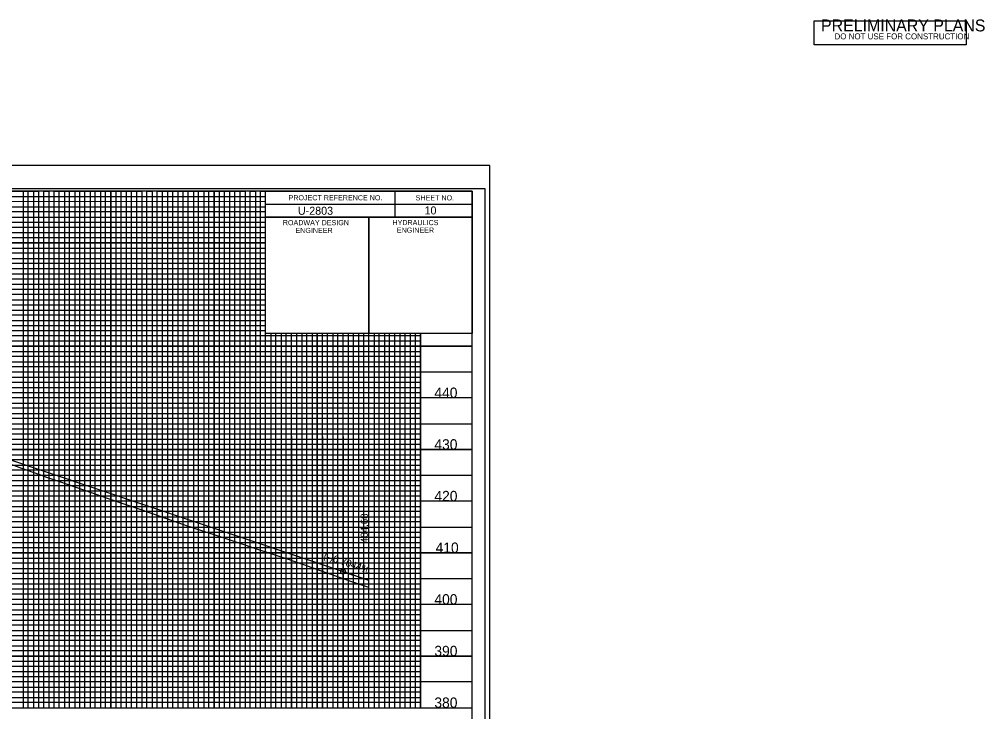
# Model space of a CAD drawing. Extents: x 571503 to 593215, y -77195 to -51828.
# Drawn here: x 583558 to 584493, y -73444 to -72774 of the extents above; entities that cross this region are included whole.
import ezdxf

# ---------------------------------------------------------------- set-up
doc = ezdxf.new("R2010")
doc.units = 0
for name, color, linetype in [('Exist Vertical Profile Ground Line', 7, 'Continuous'), ('Exist Vertical Profile Vertical Axis Label', 7, 'Continuous'), ('Prop Vertical Profile Curve Label', 7, 'Continuous'), ('Prop Vertical Profile Grade', 7, 'Continuous'), ('Prop Vertical Profile Grade Label', 7, 'Continuous'), ('Prop VPI Label', 7, 'Continuous'), ('Sheet Cutting Line CELL', 7, 'Continuous'), ('Sheet Data Field CELL', 7, 'Continuous'), ('Sheet DOT Grid CELL', 7, 'Continuous'), ('Sheet Layout Profile Border Port 1', 7, 'Continuous'), ('Sheet Plot Border Inside CELL', 7, 'Continuous'), ('Sheet Plot Border Outside CELL', 7, 'Continuous'), ('Sheet Profile CELL', 7, 'Continuous'), ('Sheet Profile Grid Major CELL', 7, 'Continuous'), ('Sheet Profile Grid Middle CELL', 7, 'Continuous'), ('Sheet Profile Grid Minor CELL', 7, 'Continuous'), ('Sheet Sticker Preliminary CELL', 7, 'Continuous')]:
    doc.layers.add(name, color=color, linetype=linetype)

msp = doc.modelspace()

# ---------------------------------------------------------------- linework, layer by layer
at = {"layer": 'Exist Vertical Profile Ground Line'}
msp.add_lwpolyline([(583546.65, -73202.89), (583560.54, -73207.95), (583578.03, -73214.22), (583584.69, -73216.65), (583597.14, -73220.9), (583612.11, -73226.16), (583629.03, -73231.94), (583637.11, -73234.78), (583645.46, -73237.64), (583660.73, -73242.98), (583677.05, -73248.56), (583685.27, -73251.43), (583689.87, -73253.04), (583705.42, -73258.32), (583722.05, -73264.12), (583724.42, -73264.93), (583728.62, -73266.35), (583743.88, -73271.4), (583760.39, -73276.98), (583770.95, -73280.48), (583787.27, -73286), (583802.9, -73290.98), (583809.77, -73293.33), (583817.86, -73295.91), (583833.67, -73301.33), (583849.88, -73307.04), (583857.24, -73309.62), (583864.77, -73312.28), (583880.15, -73317.68), (583896.73, -73323.36), (583896.98, -73323.45)], dxfattribs=at)
at = {"layer": 'Prop Vertical Profile Curve Label'}
msp.add_circle((583871.98, -73308.26), 2.25, dxfattribs=at)
at = {"layer": 'Prop Vertical Profile Grade'}
msp.add_line((583521.98, -73190.93), (583871.98, -73308.26), dxfattribs=at)
msp.add_open_spline([(583871.98, -73308.26), (583873.75, -73308.85), (583875.52, -73309.45), (583877.28, -73310.04), (583879.05, -73310.63), (583880.82, -73311.23), (583882.58, -73311.82), (583884.35, -73312.41), (583886.12, -73313.01), (583887.88, -73313.6), (583889.65, -73314.2), (583891.42, -73314.79), (583893.18, -73315.39), (583894.45, -73315.82), (583895.72, -73316.25), (583896.98, -73316.67)], degree=3, dxfattribs=at)
at = {"layer": 'Prop VPI Label'}
msp.add_line((583871.98, -73308.26), (583896.98, -73316.64), dxfattribs=at)
at = {"layer": 'Sheet Cutting Line CELL'}
msp.add_line((584013.98, -72915.09), (582329.98, -72915.09), dxfattribs=at)
at = {"layer": 'Sheet DOT Grid CELL'}
for p, q in [((583596.98, -73440.09), (583596.98, -72940.09)), ((583646.98, -73440.09), (583646.98, -72940.09)), ((583696.98, -73440.09), (583696.98, -72940.09)), ((583746.98, -73440.09), (583746.98, -72940.09)), ((583796.93, -72990.09), (582496.98, -72990.09)), ((583796.93, -73040.09), (582496.98, -73040.09)), ((583796.98, -73440.09), (583796.98, -73077.64)), ((583846.98, -73440.09), (583846.98, -73077.64)), ((583896.98, -73440.09), (583896.98, -73077.64)), ((583946.98, -73440.09), (583946.98, -73077.64)), ((583996.98, -73090.09), (582496.98, -73090.09)), ((583996.98, -73140.09), (582496.98, -73140.09)), ((583996.98, -73190.09), (582496.98, -73190.09)), ((583996.98, -73240.09), (582496.98, -73240.09)), ((583996.98, -73290.09), (582496.98, -73290.09)), ((583996.98, -73340.09), (582496.98, -73340.09)), ((583996.98, -73390.09), (582496.98, -73390.09))]:
    msp.add_line(p, q, dxfattribs=at)
at = {"layer": 'Sheet Layout Profile Border Port 1'}
msp.add_lwpolyline([(582546.98, -72940.09), (582546.98, -73440.09), (583946.98, -73440.09), (583946.98, -73077.64), (583796.93, -73077.64), (583796.93, -72940.09)], close=True, dxfattribs=at)
at = {"layer": 'Sheet Plot Border Inside CELL'}
msp.add_lwpolyline([(582342.98, -73992.64), (584009.48, -73992.64), (584009.48, -72937.54), (582342.98, -72937.54)], close=True, dxfattribs=at)
at = {"layer": 'Sheet Plot Border Outside CELL'}
msp.add_lwpolyline([(582329.98, -74015.09), (584013.98, -74015.09), (584013.98, -72915.09), (582329.98, -72915.09)], close=True, dxfattribs=at)
at = {"layer": 'Sheet Profile CELL'}
for p, q in [((583921.98, -72940.14), (583921.98, -72965.14)), ((583796.93, -72952.64), (583996.98, -72952.64)), ((583896.98, -72965.14), (583896.98, -73077.59)), ((582496.98, -73440.09), (583996.98, -73440.09))]:
    msp.add_line(p, q, dxfattribs=at)
for points in [[(583996.98, -72940.09), (582496.98, -72940.09), (582496.98, -73990.09), (583996.98, -73990.09)], [(583796.93, -72940.09), (583996.98, -72940.09), (583996.98, -72965.14), (583796.93, -72965.14)], [(583796.93, -72965.14), (583896.98, -72965.14), (583896.98, -73077.64), (583796.93, -73077.64)], [(583896.98, -72965.14), (583996.98, -72965.14), (583996.98, -73077.64), (583896.98, -73077.64)]]:
    msp.add_lwpolyline(points, close=True, dxfattribs=at)
at = {"layer": 'Sheet Profile Grid Major CELL'}
for points in [[(583546.98, -73440.09), (583596.98, -73440.09), (583596.98, -72940.09), (583646.98, -72940.09), (583646.98, -73440.09), (583696.98, -73440.09), (583696.98, -72940.09), (583746.98, -72940.09), (583746.98, -73440.09), (583796.98, -73440.09), (583796.98, -72940.09), (583823.28, -72940.09)], [(582496.98, -72990.09), (583796.98, -72990.09)], [(583796.98, -73040.09), (582496.98, -73040.09), (582496.98, -73090.09), (583996.98, -73090.09)], [(583846.98, -73077.64), (583846.98, -73440.09), (583896.98, -73440.09), (583896.98, -73440.09), (583896.98, -73077.64)], [(583946.98, -73077.64), (583946.98, -73440.09), (583996.98, -73440.09), (583996.98, -73090.09)], [(583996.98, -73140.09), (582496.98, -73140.09), (582496.98, -73190.09), (583996.98, -73190.09)], [(583996.98, -73240.09), (582496.98, -73240.09), (582496.98, -73290.09), (583996.98, -73290.09)], [(583996.98, -73340.09), (582496.98, -73340.09), (582496.98, -73340.09), (582496.98, -73390.09), (583996.98, -73390.09)]]:
    msp.add_lwpolyline(points, dxfattribs=at)
at = {"layer": 'Sheet Profile Grid Middle CELL'}
msp.add_line((582496.98, -72965.09), (583796.93, -72965.09), dxfattribs=at)
for points in [[(583521.98, -72940.09), (583571.98, -72940.09), (583571.98, -73440.09), (583621.98, -73440.09), (583621.98, -72940.09), (583671.98, -72940.09), (583671.98, -73440.09), (583721.98, -73440.09), (583721.98, -72940.09), (583771.98, -72940.09), (583771.98, -73440.09), (583821.98, -73440.09), (583821.98, -73077.64)], [(583796.98, -73015.09), (582496.98, -73015.09), (582496.98, -73065.09), (583796.98, -73065.09)], [(583821.98, -73177.29), (583821.98, -73440.09), (583871.98, -73440.09), (583871.98, -73077.64)], [(583871.98, -73177.29), (583871.98, -73440.09), (583921.98, -73440.09), (583921.98, -73077.64)], [(583996.98, -73115.09), (582496.98, -73115.09), (582496.98, -73165.09), (583821.98, -73165.09)], [(583821.98, -73165.09), (583996.98, -73165.09)], [(583996.98, -73215.09), (582496.98, -73215.09), (582496.98, -73265.09), (583996.98, -73265.09)], [(583996.98, -73315.09), (582496.98, -73315.09), (582496.98, -73365.09), (583996.98, -73365.09)], [(583996.98, -73415.09), (582496.98, -73415.09)]]:
    msp.add_lwpolyline(points, dxfattribs=at)
at = {"layer": 'Sheet Profile Grid Minor CELL'}
for p, q in [((582546.98, -72945.09), (583796.98, -72945.09)), ((583796.98, -72950.09), (582546.98, -72950.44)), ((582546.98, -72955.09), (583796.98, -72955.09)), ((583796.93, -73075.09), (582546.98, -73075.09)), ((583946.98, -73080.09), (582546.98, -73080.09)), ((583946.98, -73085.09), (582546.98, -73085.09)), ((582546.98, -73095.09), (583946.98, -73095.09)), ((583946.98, -73100.09), (582546.98, -73100.09)), ((582546.98, -73105.09), (583946.98, -73105.09)), ((583946.98, -73125.09), (582546.98, -73125.09)), ((582546.98, -73130.09), (583946.98, -73130.09)), ((583946.98, -73150.09), (582546.98, -73150.09)), ((582546.98, -73155.09), (583946.98, -73155.09)), ((583946.98, -73175.09), (582546.98, -73175.09)), ((582546.98, -73180.09), (583946.98, -73180.09)), ((583946.98, -73185.09), (582546.98, -73185.09)), ((582546.98, -73195.09), (583946.98, -73195.09)), ((583946.98, -73200.09), (582546.98, -73200.09)), ((582546.98, -73205.09), (583946.98, -73205.09)), ((583946.98, -73210.09), (582546.98, -73210.09)), ((582546.98, -73220.09), (583946.98, -73220.09)), ((583946.98, -73225.09), (582546.98, -73225.09)), ((582546.98, -73230.09), (583946.98, -73230.09)), ((583946.98, -73235.09), (582546.98, -73235.09)), ((582546.98, -73245.09), (583946.98, -73245.09)), ((583946.98, -73250.09), (582546.98, -73250.09)), ((582546.98, -73255.09), (583946.98, -73255.09)), ((583946.98, -73260.09), (582546.98, -73260.09)), ((582546.98, -73270.09), (583946.98, -73270.09)), ((583946.98, -73275.09), (582546.98, -73275.09)), ((582546.98, -73280.09), (583946.98, -73280.09)), ((583946.98, -73285.09), (582546.98, -73285.09)), ((582546.98, -73295.09), (583946.98, -73295.09)), ((583946.98, -73300.09), (582546.98, -73300.09)), ((582546.98, -73305.09), (583946.98, -73305.09)), ((583946.98, -73310.09), (582546.98, -73310.09)), ((582546.98, -73320.09), (583946.98, -73320.09)), ((583946.98, -73325.09), (582546.98, -73325.09)), ((583946.98, -73330.09), (582546.98, -73330.09)), ((583946.98, -73335.09), (582546.98, -73335.09)), ((582546.98, -73345.09), (583946.98, -73345.09)), ((583946.98, -73350.09), (582546.98, -73350.09)), ((582546.98, -73355.09), (583946.98, -73355.09)), ((583946.98, -73360.09), (582546.98, -73360.09)), ((582546.98, -73370.09), (583946.98, -73370.09)), ((583946.98, -73375.09), (582546.98, -73375.09)), ((582546.98, -73380.09), (583946.98, -73380.09)), ((583946.98, -73385.09), (582546.98, -73385.09)), ((582546.98, -73395.09), (583946.98, -73395.09)), ((583946.98, -73400.09), (582546.98, -73400.09)), ((582546.98, -73405.09), (583946.98, -73405.09)), ((583946.98, -73410.09), (582546.98, -73410.09)), ((582546.98, -73420.09), (583946.98, -73420.09)), ((583946.98, -73425.09), (582546.98, -73425.09)), ((582546.98, -73430.09), (583946.98, -73430.09))]:
    msp.add_line(p, q, dxfattribs=at)
for points in [[(583556.98, -72940.09), (583561.98, -72940.09), (583561.98, -73440.09), (583566.98, -73440.09), (583566.98, -72940.09), (583576.98, -72940.09), (583576.98, -73440.09), (583581.98, -73440.09), (583581.98, -72940.09), (583586.98, -72940.09), (583586.98, -73440.09), (583591.98, -73440.09), (583591.98, -72940.09), (583601.98, -72940.09), (583601.98, -73440.09), (583606.98, -73440.09), (583606.98, -72940.09), (583611.98, -72940.09), (583611.98, -73440.09), (583616.98, -73440.09), (583616.98, -72940.09), (583626.98, -72940.09), (583626.98, -73440.09), (583631.98, -73440.09), (583631.98, -72940.09), (583636.98, -72940.09), (583636.98, -73440.09), (583641.98, -73440.09), (583641.98, -72940.09), (583651.98, -72940.09), (583651.98, -73440.09), (583656.98, -73440.09), (583656.98, -72940.09), (583661.98, -72940.09), (583661.98, -73440.09), (583666.98, -73440.09), (583666.98, -72940.09), (583676.98, -72940.09), (583676.98, -73440.09), (583681.98, -73440.09), (583681.98, -72940.09), (583686.98, -72940.09), (583686.98, -73440.09)], [(583686.98, -73440.09), (583691.98, -73440.09), (583691.98, -72940.09), (583701.98, -72940.09), (583701.98, -73440.09), (583706.98, -73440.09), (583706.98, -72940.09), (583711.98, -72940.09), (583711.98, -73440.09), (583716.98, -73440.09), (583716.98, -72940.09), (583726.98, -72940.09), (583726.98, -73440.09), (583731.98, -73440.09), (583731.98, -72940.09), (583736.98, -72940.09), (583736.98, -73440.09), (583741.98, -73440.09), (583741.98, -72940.09), (583751.98, -72940.09), (583751.98, -73440.09), (583756.98, -73440.09), (583756.98, -72940.09), (583761.98, -72940.09), (583761.98, -73440.09), (583766.98, -73440.09), (583766.98, -72940.09), (583776.98, -72940.09), (583776.98, -73440.09), (583781.98, -73440.09), (583781.98, -72940.09), (583786.98, -72940.09), (583786.98, -73440.09), (583791.98, -73440.09), (583791.98, -72940.09), (583801.98, -72940.09)], [(583796.98, -72960.09), (582546.98, -72960.09), (582546.98, -72970.09), (583796.98, -72970.09)], [(583796.93, -72975.09), (582546.98, -72975.09), (582546.98, -72980.09), (583796.98, -72980.09)], [(583796.98, -72985.09), (582546.98, -72985.09), (582546.98, -72995.09), (583796.98, -72995.09)], [(583796.98, -73000.09), (582546.98, -73000.09), (582546.98, -73005.09), (583796.98, -73005.09)], [(583796.98, -73010.09), (582546.98, -73010.09), (582546.98, -73020.09), (583796.98, -73020.09)], [(583796.98, -73025.09), (582546.98, -73025.09), (582546.98, -73030.09), (583796.98, -73030.09)], [(583796.98, -73035.09), (582546.98, -73035.09), (582546.98, -73045.09), (583796.98, -73045.09)], [(583796.98, -73050.19), (582547.08, -73050.19), (582547.08, -73055.09), (583796.98, -73055.09)], [(583796.98, -73060.09), (582546.98, -73060.09), (582546.98, -73070.09), (583796.98, -73070.09)], [(583801.98, -73077.64), (583801.98, -73440.09), (583806.98, -73440.09), (583806.98, -73077.64)], [(583811.98, -73077.64), (583811.98, -73440.09), (583816.98, -73440.09), (583816.98, -73077.64)], [(583826.98, -73077.64), (583826.98, -73440.09), (583826.98, -73440.09), (583831.98, -73440.09), (583836.98, -73440.09), (583836.98, -73077.64)], [(583831.98, -73077.64), (583831.98, -73440.09)], [(583841.98, -73077.64), (583841.88, -73440.04), (583846.88, -73440.04), (583851.98, -73440.09), (583851.98, -73077.64)], [(583851.98, -73177.29), (583851.98, -73440.09), (583856.98, -73440.09), (583856.98, -73077.64)], [(583861.98, -73077.64), (583861.98, -73440.09), (583866.98, -73440.09), (583866.98, -73077.64)], [(583876.98, -73077.64), (583876.98, -73440.09), (583881.98, -73440.09), (583881.98, -73077.64)], [(583886.98, -73077.64), (583886.98, -73440.09), (583891.98, -73440.09), (583891.98, -73077.64)], [(583901.98, -73077.64), (583901.98, -73440.09), (583906.98, -73440.09), (583906.98, -73077.64)], [(583911.98, -73077.64), (583911.98, -73440.09), (583916.98, -73440.09), (583916.98, -73077.64)], [(583926.98, -73077.64), (583926.98, -73440.09), (583931.98, -73440.09), (583931.98, -73077.64)], [(583936.98, -73077.64), (583936.98, -73440.09), (583941.98, -73440.09), (583941.98, -73077.64)], [(583946.98, -73110.09), (582546.98, -73110.09), (582546.98, -73120.09), (583946.98, -73120.09)], [(583946.98, -73135.09), (582546.98, -73135.09), (582546.98, -73145.09), (583946.98, -73145.09)], [(583946.98, -73160.09), (582546.98, -73160.09), (582546.98, -73170.09), (583946.98, -73170.09)], [(583946.98, -73435.09), (582546.98, -73435.09)]]:
    msp.add_lwpolyline(points, dxfattribs=at)
at = {"layer": 'Sheet Sticker Preliminary CELL'}
msp.add_lwpolyline([(584328.41, -72798.41), (584328.41, -72774.91), (584475.41, -72774.91), (584475.41, -72798.41)], close=True, dxfattribs=at)

# ---------------------------------------------------------------- texts
at = {"layer": 'Exist Vertical Profile Vertical Axis Label'}
for s, p in [('440', (583960.42, -73140.09)), ('430', (583960.42, -73190.09)), ('420', (583960.42, -73240.09)), ('410', (583961.61, -73290.09)), ('400', (583960.42, -73340.09)), ('390', (583960.42, -73390.09)), ('380', (583960.42, -73440.09))]:
    msp.add_text(s, height=10, dxfattribs=at).set_placement(p)
at = {"layer": 'Prop Vertical Profile Grade Label'}
msp.add_text('(-)6.7044%', height=7, rotation=341.46781, dxfattribs=at).set_placement((583852.63, -73295.58))
at = {"layer": 'Prop VPI Label'}
msp.add_text('404.68', height=7, rotation=90, dxfattribs=at).set_placement((583895.98, -73280.6))
at = {"layer": 'Sheet Data Field CELL'}
for s, p in [('U-2803   ', (583828.25, -72962.78)), ('10 ', (583950.89, -72962.48))]:
    msp.add_text(s, height=7.75, dxfattribs=at).set_placement(p)
at = {"layer": 'Sheet Profile CELL'}
for s, height, p in [('PROJECT REFERENCE NO.', 5.0001, (583819.15, -72948.78)), ('SHEET NO.', 5, (583942.3, -72948.88)), ('ROADWAY DESIGN', 5.0001, (583813.6, -72972.88)), ('HYDRAULICS', 5, (583919.8, -72972.83)), ('ENGINEER', 5, (583825.85, -72980.48)), ('ENGINEER', 5, (583924.05, -72980.18))]:
    msp.add_text(s, height=height, dxfattribs=at).set_placement(p)
at = {"layer": 'Sheet Sticker Preliminary CELL'}
for s, height, p in [('PRELIMINARY PLANS', 11.52, (584334.91, -72785.26)), ('DO NOT USE FOR CONSTRUCTION', 5.76, (584348.01, -72792.96))]:
    msp.add_text(s, height=height, dxfattribs=at).set_placement(p)

doc.saveas('drawing.dxf')
